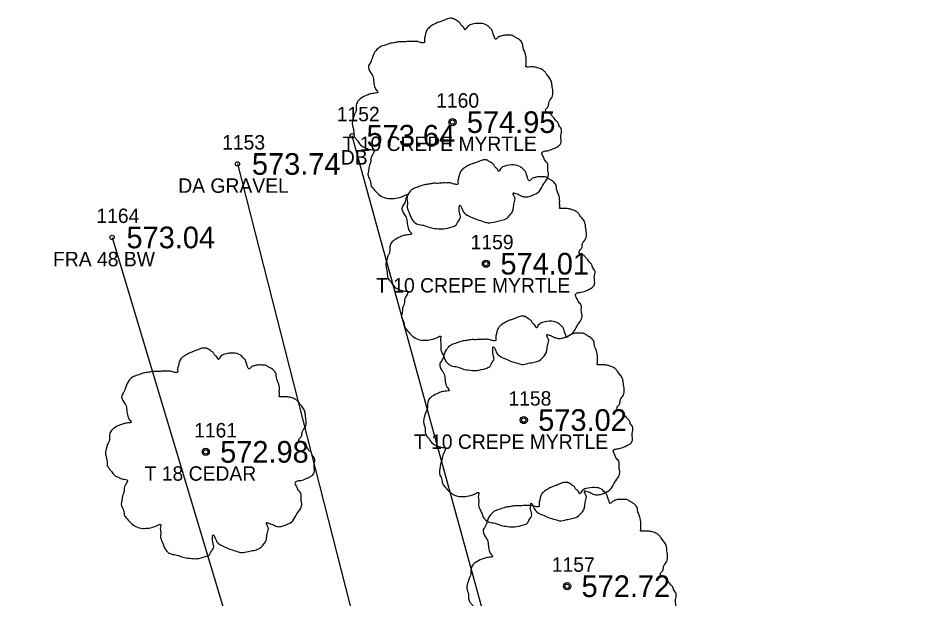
# Model space of a CAD drawing. Extents: x 1529475 to 1532053, y 876698 to 877911.
# Drawn here: x 1531018 to 1531081.1, y 877352.1 to 877392.4 of the extents above; entities that cross this region are included whole.
import ezdxf

# ---------------------------------------------------------------- set-up
doc = ezdxf.new("R2010")
doc.units = 0
for name, color, linetype in [('RD_EX_Driveway', 7, 'Continuous'), ('RD_EX_Driveway_txCode', 7, 'Continuous'), ('RD_EX_Fence_Other', 7, 'Continuous'), ('RD_EX_Fence_Other_txCode', 7, 'Continuous'), ('RD_EX_TX_Driveway_ELEV', 7, 'Continuous'), ('RD_EX_TX_Fence_Other_ELEV', 7, 'Continuous'), ('RD_EX_TX_VEG_ELEV', 7, 'Continuous'), ('RD_EX_VEG', 7, 'Continuous'), ('RD_EX_VEG_txCode', 7, 'Continuous'), ('RD_SMD_Locator', 7, 'Continuous')]:
    doc.layers.add(name, color=color, linetype=linetype)

msp = doc.modelspace()

# ---------------------------------------------------------------- linework, layer by layer
at = {"layer": 'RD_EX_Driveway'}
for points in [[(1531081.114, 877292.384), (1531071.715, 877299.875), (1531056.729, 877327.604), (1531041.174, 877384.235)], [(1531033.235, 877382.278), (1531052.392, 877307.085), (1531047.892, 877296.694), (1531044.444, 877291.901), (1531038.69, 877288.667)]]:
    msp.add_lwpolyline(points, dxfattribs=at)
at = {"layer": 'RD_EX_Fence_Other'}
msp.add_lwpolyline([(1531024.548, 877377.186), (1531037.254, 877334.843), (1531041.631, 877306.635), (1530974.749, 877305.169), (1530894.744, 877304.424), (1530859.113, 877317.256)], dxfattribs=at)
at = {"layer": 'RD_EX_VEG'}
for centre, radius in [((1531048.121, 877385.178), 0.25), ((1531048.108, 877385.16), 0.0001), ((1531050.446, 877375.367), 0.25), ((1531050.434, 877375.348), 0.0001), ((1531053.063, 877364.532), 0.25), ((1531053.051, 877364.513), 0.0001), ((1531031.035, 877362.328), 0.25), ((1531031.022, 877362.309), 0.0001), ((1531056.065, 877353.015), 0.25), ((1531056.052, 877352.996), 0.0001)]:
    msp.add_circle(centre, radius, dxfattribs=at)
for points in [[(1531048.253, 877392.346), (1531047.953, 877392.371), (1531047.628, 877392.271), (1531047.378, 877392.171), (1531047.153, 877392.096), (1531046.928, 877391.996), (1531046.629, 877391.821), (1531046.404, 877391.621), (1531046.279, 877391.371), (1531046.229, 877391.146), (1531046.179, 877390.871), (1531046.179, 877390.696), (1531046.054, 877390.671), (1531045.904, 877390.696), (1531045.654, 877390.771), (1531045.404, 877390.771), (1531045.154, 877390.771), (1531044.804, 877390.746), (1531044.454, 877390.746), (1531044.18, 877390.696), (1531043.855, 877390.646), (1531043.48, 877390.521), (1531043.13, 877390.396), (1531042.83, 877390.147), (1531042.58, 877389.672), (1531042.455, 877389.322), (1531042.305, 877389.072), (1531042.455, 877388.622), (1531042.63, 877388.272), (1531042.655, 877388.072), (1531042.73, 877387.648), (1531042.83, 877387.423), (1531042.955, 877387.223), (1531042.88, 877387.198), (1531042.505, 877387.148), (1531042.205, 877387.048), (1531041.781, 877386.823), (1531041.556, 877386.598), (1531041.456, 877386.273), (1531041.431, 877385.923), (1531041.331, 877385.724), (1531041.256, 877385.449), (1531041.231, 877385.374), (1531041.181, 877385.049), (1531041.281, 877384.599), (1531041.306, 877384.249), (1531041.431, 877384.024), (1531041.581, 877383.849), (1531041.756, 877383.599), (1531042.155, 877383.375), (1531042.48, 877383.275), (1531042.68, 877383.25), (1531042.505, 877382.75), (1531042.455, 877382.4), (1531042.33, 877382), (1531042.33, 877381.925), (1531042.28, 877381.45), (1531042.43, 877381.125), (1531042.505, 877380.751), (1531042.68, 877380.526), (1531042.955, 877380.226), (1531043.28, 877380.001), (1531043.78, 877379.876), (1531044.18, 877379.901), (1531044.754, 877380.076), (1531045.004, 877380.151), (1531044.979, 877379.976), (1531045.004, 877379.601), (1531045.004, 877379.176), (1531045.154, 877378.852), (1531045.254, 877378.577), (1531045.404, 877378.327), (1531045.729, 877378.102), (1531046.129, 877378.027), (1531046.554, 877377.877), (1531047.003, 877377.802), (1531047.503, 877377.777), (1531048.103, 877377.927), (1531048.378, 877378.052), (1531048.478, 877378.227), (1531048.678, 877378.602), (1531048.628, 877378.827), (1531048.653, 877379.426), (1531048.753, 877379.251), (1531048.928, 877378.901), (1531049.427, 877378.602), (1531049.827, 877378.427), (1531050.302, 877378.277), (1531050.602, 877378.202), (1531051.077, 877378.277), (1531051.451, 877378.352), (1531051.826, 877378.477), (1531052.126, 877378.752), (1531052.301, 877379.026), (1531052.351, 877379.301), (1531052.426, 877379.676), (1531052.476, 877379.851)], [(1531052.476, 877379.851), (1531052.401, 877380.026), (1531052.351, 877380.276), (1531052.426, 877380.251), (1531052.601, 877380.201), (1531052.876, 877380.076), (1531053.101, 877380.001), (1531053.426, 877380.026), (1531053.7, 877380.126), (1531054.15, 877380.401), (1531054.425, 877380.876), (1531054.7, 877381.275), (1531054.775, 877381.6), (1531054.725, 877381.825), (1531054.7, 877382.325), (1531054.5, 877382.575), (1531054.45, 877382.7), (1531054.35, 877383.1), (1531054.425, 877383.15), (1531054.7, 877383.2), (1531055.075, 877383.325), (1531055.35, 877383.449), (1531055.575, 877383.624), (1531055.65, 877383.849), (1531055.625, 877384.249), (1531055.675, 877384.649), (1531055.6, 877384.799), (1531055.5, 877384.949), (1531055.425, 877385.149), (1531055.275, 877385.299), (1531055.175, 877385.449), (1531055.075, 877385.549), (1531054.95, 877385.699), (1531054.775, 877385.823), (1531054.625, 877385.873), (1531054.575, 877386.023), (1531054.725, 877386.223), (1531054.775, 877386.323), (1531054.8, 877386.548), (1531055.025, 877386.898), (1531055.075, 877387.298), (1531055.025, 877387.723), (1531054.975, 877387.998), (1531054.825, 877388.272), (1531054.625, 877388.522), (1531054.5, 877388.697), (1531054.325, 877388.822), (1531054, 877388.947), (1531053.75, 877388.997), (1531053.401, 877388.997), (1531053.201, 877389.047), (1531053.226, 877389.097), (1531053.226, 877389.247), (1531053.226, 877389.522), (1531053.151, 877389.972), (1531053.001, 877390.471), (1531053.001, 877390.496), (1531052.901, 877390.746), (1531052.676, 877390.946), (1531052.501, 877391.046), (1531052.301, 877391.171), (1531052.051, 877391.196), (1531051.751, 877391.196), (1531051.476, 877391.146), (1531051.276, 877391.046), (1531051.102, 877390.921), (1531051.027, 877391.071), (1531050.927, 877391.371), (1531050.877, 877391.521), (1531050.727, 877391.696), (1531050.502, 877391.896), (1531050.052, 877392.021), (1531049.427, 877391.946), (1531049.127, 877391.746), (1531048.977, 877391.571), (1531048.928, 877391.696), (1531048.728, 877391.896), (1531048.628, 877392.071), (1531048.453, 877392.196), (1531048.303, 877392.296), (1531048.203, 877392.346)], [(1531050.578, 877382.534), (1531050.278, 877382.559), (1531049.953, 877382.459), (1531049.704, 877382.359), (1531049.479, 877382.284), (1531049.254, 877382.184), (1531048.954, 877382.009), (1531048.729, 877381.809), (1531048.604, 877381.559), (1531048.554, 877381.334), (1531048.504, 877381.06), (1531048.504, 877380.885), (1531048.379, 877380.86), (1531048.229, 877380.885), (1531047.979, 877380.96), (1531047.729, 877380.96), (1531047.479, 877380.96), (1531047.13, 877380.935), (1531046.78, 877380.935), (1531046.505, 877380.885), (1531046.18, 877380.835), (1531045.805, 877380.71), (1531045.455, 877380.585), (1531045.156, 877380.335), (1531044.906, 877379.86), (1531044.781, 877379.51), (1531044.631, 877379.26), (1531044.781, 877378.811), (1531044.956, 877378.461), (1531044.981, 877378.261), (1531045.056, 877377.836), (1531045.156, 877377.611), (1531045.28, 877377.411), (1531045.206, 877377.386), (1531044.831, 877377.336), (1531044.531, 877377.236), (1531044.106, 877377.011), (1531043.881, 877376.786), (1531043.781, 877376.462), (1531043.756, 877376.112), (1531043.656, 877375.912), (1531043.581, 877375.637), (1531043.556, 877375.562), (1531043.506, 877375.237), (1531043.606, 877374.787), (1531043.631, 877374.437), (1531043.756, 877374.213), (1531043.906, 877374.038), (1531044.081, 877373.788), (1531044.481, 877373.563), (1531044.806, 877373.463), (1531045.006, 877373.438), (1531044.831, 877372.938), (1531044.781, 877372.588), (1531044.656, 877372.188), (1531044.656, 877372.114), (1531044.606, 877371.639), (1531044.756, 877371.314), (1531044.831, 877370.939), (1531045.006, 877370.714), (1531045.28, 877370.414), (1531045.605, 877370.189), (1531046.105, 877370.064), (1531046.505, 877370.089), (1531047.08, 877370.264), (1531047.33, 877370.339), (1531047.305, 877370.164), (1531047.33, 877369.789), (1531047.33, 877369.365), (1531047.479, 877369.04), (1531047.579, 877368.765), (1531047.729, 877368.515), (1531048.054, 877368.29), (1531048.454, 877368.215), (1531048.879, 877368.065), (1531049.329, 877367.99), (1531049.828, 877367.965), (1531050.428, 877368.115), (1531050.703, 877368.24), (1531050.803, 877368.415), (1531051.003, 877368.79), (1531050.953, 877369.015), (1531050.978, 877369.615), (1531051.078, 877369.44), (1531051.253, 877369.09), (1531051.753, 877368.79), (1531052.152, 877368.615), (1531052.627, 877368.465), (1531052.927, 877368.39), (1531053.402, 877368.465), (1531053.777, 877368.54), (1531054.152, 877368.665), (1531054.451, 877368.94), (1531054.626, 877369.215), (1531054.676, 877369.49), (1531054.751, 877369.864), (1531054.801, 877370.039)], [(1531054.801, 877370.039), (1531054.726, 877370.214), (1531054.676, 877370.464), (1531054.751, 877370.439), (1531054.926, 877370.389), (1531055.201, 877370.264), (1531055.426, 877370.189), (1531055.751, 877370.214), (1531056.026, 877370.314), (1531056.476, 877370.589), (1531056.75, 877371.064), (1531057.025, 877371.464), (1531057.1, 877371.789), (1531057.05, 877372.014), (1531057.025, 877372.513), (1531056.825, 877372.763), (1531056.775, 877372.888), (1531056.675, 877373.288), (1531056.75, 877373.338), (1531057.025, 877373.388), (1531057.4, 877373.513), (1531057.675, 877373.638), (1531057.9, 877373.813), (1531057.975, 877374.038), (1531057.95, 877374.437), (1531058, 877374.837), (1531057.925, 877374.987), (1531057.825, 877375.137), (1531057.75, 877375.337), (1531057.6, 877375.487), (1531057.5, 877375.637), (1531057.4, 877375.737), (1531057.275, 877375.887), (1531057.1, 877376.012), (1531056.95, 877376.062), (1531056.9, 877376.212), (1531057.05, 877376.412), (1531057.1, 877376.512), (1531057.125, 877376.736), (1531057.35, 877377.086), (1531057.4, 877377.486), (1531057.35, 877377.911), (1531057.3, 877378.186), (1531057.15, 877378.461), (1531056.95, 877378.711), (1531056.825, 877378.886), (1531056.65, 877379.01), (1531056.326, 877379.135), (1531056.076, 877379.185), (1531055.726, 877379.185), (1531055.526, 877379.235), (1531055.551, 877379.285), (1531055.551, 877379.435), (1531055.551, 877379.71), (1531055.476, 877380.16), (1531055.326, 877380.66), (1531055.326, 877380.685), (1531055.226, 877380.935), (1531055.001, 877381.135), (1531054.826, 877381.234), (1531054.626, 877381.359), (1531054.376, 877381.384), (1531054.077, 877381.384), (1531053.802, 877381.334), (1531053.602, 877381.234), (1531053.427, 877381.11), (1531053.352, 877381.259), (1531053.252, 877381.559), (1531053.202, 877381.709), (1531053.052, 877381.884), (1531052.827, 877382.084), (1531052.377, 877382.209), (1531051.753, 877382.134), (1531051.453, 877381.934), (1531051.303, 877381.759), (1531051.253, 877381.884), (1531051.053, 877382.084), (1531050.953, 877382.259), (1531050.778, 877382.384), (1531050.628, 877382.484), (1531050.528, 877382.534)], [(1531053.195, 877371.699), (1531052.895, 877371.724), (1531052.57, 877371.624), (1531052.32, 877371.524), (1531052.096, 877371.449), (1531051.871, 877371.349), (1531051.571, 877371.174), (1531051.346, 877370.974), (1531051.221, 877370.724), (1531051.171, 877370.5), (1531051.121, 877370.225), (1531051.121, 877370.05), (1531050.996, 877370.025), (1531050.846, 877370.05), (1531050.596, 877370.125), (1531050.346, 877370.125), (1531050.096, 877370.125), (1531049.747, 877370.1), (1531049.397, 877370.1), (1531049.122, 877370.05), (1531048.797, 877370), (1531048.422, 877369.875), (1531048.072, 877369.75), (1531047.772, 877369.5), (1531047.523, 877369.025), (1531047.398, 877368.675), (1531047.248, 877368.425), (1531047.398, 877367.976), (1531047.573, 877367.626), (1531047.597, 877367.426), (1531047.672, 877367.001), (1531047.772, 877366.776), (1531047.897, 877366.576), (1531047.822, 877366.551), (1531047.448, 877366.501), (1531047.148, 877366.401), (1531046.723, 877366.176), (1531046.498, 877365.952), (1531046.398, 877365.627), (1531046.373, 877365.277), (1531046.273, 877365.077), (1531046.198, 877364.802), (1531046.173, 877364.727), (1531046.123, 877364.402), (1531046.223, 877363.952), (1531046.248, 877363.603), (1531046.373, 877363.378), (1531046.523, 877363.203), (1531046.698, 877362.953), (1531047.098, 877362.728), (1531047.423, 877362.628), (1531047.622, 877362.603), (1531047.448, 877362.103), (1531047.398, 877361.753), (1531047.273, 877361.354), (1531047.273, 877361.279), (1531047.223, 877360.804), (1531047.373, 877360.479), (1531047.448, 877360.104), (1531047.622, 877359.879), (1531047.897, 877359.579), (1531048.222, 877359.354), (1531048.722, 877359.229), (1531049.122, 877359.254), (1531049.697, 877359.429), (1531049.946, 877359.504), (1531049.921, 877359.329), (1531049.946, 877358.955), (1531049.946, 877358.53), (1531050.096, 877358.205), (1531050.196, 877357.93), (1531050.346, 877357.68), (1531050.671, 877357.455), (1531051.071, 877357.38), (1531051.496, 877357.23), (1531051.946, 877357.155), (1531052.445, 877357.13), (1531053.045, 877357.28), (1531053.32, 877357.405), (1531053.42, 877357.58), (1531053.62, 877357.955), (1531053.57, 877358.18), (1531053.595, 877358.78), (1531053.695, 877358.605), (1531053.87, 877358.255), (1531054.37, 877357.955), (1531054.769, 877357.78), (1531055.244, 877357.63), (1531055.544, 877357.555), (1531056.019, 877357.63), (1531056.394, 877357.705), (1531056.768, 877357.83), (1531057.068, 877358.105), (1531057.243, 877358.38), (1531057.293, 877358.655), (1531057.368, 877359.03), (1531057.418, 877359.204)], [(1531057.418, 877359.204), (1531057.343, 877359.379), (1531057.293, 877359.629), (1531057.368, 877359.604), (1531057.543, 877359.554), (1531057.818, 877359.429), (1531058.043, 877359.354), (1531058.368, 877359.379), (1531058.643, 877359.479), (1531059.092, 877359.754), (1531059.367, 877360.229), (1531059.642, 877360.629), (1531059.717, 877360.954), (1531059.667, 877361.179), (1531059.642, 877361.678), (1531059.442, 877361.928), (1531059.392, 877362.053), (1531059.292, 877362.453), (1531059.367, 877362.503), (1531059.642, 877362.553), (1531060.017, 877362.678), (1531060.292, 877362.803), (1531060.517, 877362.978), (1531060.592, 877363.203), (1531060.567, 877363.603), (1531060.617, 877364.002), (1531060.542, 877364.152), (1531060.442, 877364.302), (1531060.367, 877364.502), (1531060.217, 877364.652), (1531060.117, 877364.802), (1531060.017, 877364.902), (1531059.892, 877365.052), (1531059.717, 877365.177), (1531059.567, 877365.227), (1531059.517, 877365.377), (1531059.667, 877365.577), (1531059.717, 877365.677), (1531059.742, 877365.902), (1531059.967, 877366.251), (1531060.017, 877366.651), (1531059.967, 877367.076), (1531059.917, 877367.351), (1531059.767, 877367.626), (1531059.567, 877367.876), (1531059.442, 877368.051), (1531059.267, 877368.176), (1531058.943, 877368.301), (1531058.693, 877368.35), (1531058.343, 877368.35), (1531058.143, 877368.4), (1531058.168, 877368.45), (1531058.168, 877368.6), (1531058.168, 877368.875), (1531058.093, 877369.325), (1531057.943, 877369.825), (1531057.943, 877369.85), (1531057.843, 877370.1), (1531057.618, 877370.3), (1531057.443, 877370.4), (1531057.243, 877370.525), (1531056.993, 877370.55), (1531056.694, 877370.55), (1531056.419, 877370.5), (1531056.219, 877370.4), (1531056.044, 877370.275), (1531055.969, 877370.425), (1531055.869, 877370.724), (1531055.819, 877370.874), (1531055.669, 877371.049), (1531055.444, 877371.249), (1531054.994, 877371.374), (1531054.37, 877371.299), (1531054.07, 877371.099), (1531053.92, 877370.924), (1531053.87, 877371.049), (1531053.67, 877371.249), (1531053.57, 877371.424), (1531053.395, 877371.549), (1531053.245, 877371.649), (1531053.145, 877371.699)], [(1531031.167, 877369.495), (1531030.867, 877369.52), (1531030.542, 877369.42), (1531030.292, 877369.32), (1531030.067, 877369.245), (1531029.842, 877369.145), (1531029.542, 877368.97), (1531029.317, 877368.77), (1531029.192, 877368.52), (1531029.142, 877368.295), (1531029.092, 877368.02), (1531029.092, 877367.845), (1531028.968, 877367.82), (1531028.818, 877367.845), (1531028.568, 877367.92), (1531028.318, 877367.92), (1531028.068, 877367.92), (1531027.718, 877367.895), (1531027.368, 877367.895), (1531027.093, 877367.845), (1531026.768, 877367.796), (1531026.394, 877367.671), (1531026.044, 877367.546), (1531025.744, 877367.296), (1531025.494, 877366.821), (1531025.369, 877366.471), (1531025.219, 877366.221), (1531025.369, 877365.771), (1531025.544, 877365.422), (1531025.569, 877365.222), (1531025.644, 877364.797), (1531025.744, 877364.572), (1531025.869, 877364.372), (1531025.794, 877364.347), (1531025.419, 877364.297), (1531025.119, 877364.197), (1531024.694, 877363.972), (1531024.469, 877363.747), (1531024.369, 877363.422), (1531024.345, 877363.073), (1531024.245, 877362.873), (1531024.17, 877362.598), (1531024.145, 877362.523), (1531024.095, 877362.198), (1531024.195, 877361.748), (1531024.22, 877361.398), (1531024.345, 877361.173), (1531024.494, 877360.999), (1531024.669, 877360.749), (1531025.069, 877360.524), (1531025.394, 877360.424), (1531025.594, 877360.399), (1531025.419, 877359.899), (1531025.369, 877359.549), (1531025.244, 877359.149), (1531025.244, 877359.074), (1531025.194, 877358.6), (1531025.344, 877358.275), (1531025.419, 877357.9), (1531025.594, 877357.675), (1531025.869, 877357.375), (1531026.194, 877357.15), (1531026.694, 877357.025), (1531027.093, 877357.05), (1531027.668, 877357.225), (1531027.918, 877357.3), (1531027.893, 877357.125), (1531027.918, 877356.75), (1531027.918, 877356.326), (1531028.068, 877356.001), (1531028.168, 877355.726), (1531028.318, 877355.476), (1531028.643, 877355.251), (1531029.042, 877355.176), (1531029.467, 877355.026), (1531029.917, 877354.951), (1531030.417, 877354.926), (1531031.017, 877355.076), (1531031.291, 877355.201), (1531031.391, 877355.376), (1531031.591, 877355.751), (1531031.541, 877355.976), (1531031.566, 877356.575), (1531031.666, 877356.4), (1531031.841, 877356.051), (1531032.341, 877355.751), (1531032.741, 877355.576), (1531033.216, 877355.426), (1531033.516, 877355.351), (1531033.99, 877355.426), (1531034.365, 877355.501), (1531034.74, 877355.626), (1531035.04, 877355.901), (1531035.215, 877356.176), (1531035.265, 877356.45), (1531035.34, 877356.825), (1531035.39, 877357)], [(1531035.39, 877357), (1531035.315, 877357.175), (1531035.265, 877357.425), (1531035.34, 877357.4), (1531035.515, 877357.35), (1531035.79, 877357.225), (1531036.014, 877357.15), (1531036.339, 877357.175), (1531036.614, 877357.275), (1531037.064, 877357.55), (1531037.339, 877358.025), (1531037.614, 877358.425), (1531037.689, 877358.749), (1531037.639, 877358.974), (1531037.614, 877359.474), (1531037.414, 877359.724), (1531037.364, 877359.849), (1531037.264, 877360.249), (1531037.339, 877360.299), (1531037.614, 877360.349), (1531037.989, 877360.474), (1531038.263, 877360.599), (1531038.488, 877360.774), (1531038.563, 877360.999), (1531038.538, 877361.398), (1531038.588, 877361.798), (1531038.513, 877361.948), (1531038.413, 877362.098), (1531038.338, 877362.298), (1531038.188, 877362.448), (1531038.089, 877362.598), (1531037.989, 877362.698), (1531037.864, 877362.848), (1531037.689, 877362.973), (1531037.539, 877363.023), (1531037.489, 877363.173), (1531037.639, 877363.372), (1531037.689, 877363.472), (1531037.714, 877363.697), (1531037.939, 877364.047), (1531037.989, 877364.447), (1531037.939, 877364.872), (1531037.889, 877365.147), (1531037.739, 877365.422), (1531037.539, 877365.671), (1531037.414, 877365.846), (1531037.239, 877365.971), (1531036.914, 877366.096), (1531036.664, 877366.146), (1531036.314, 877366.146), (1531036.114, 877366.196), (1531036.139, 877366.246), (1531036.139, 877366.396), (1531036.139, 877366.671), (1531036.064, 877367.121), (1531035.914, 877367.621), (1531035.914, 877367.646), (1531035.814, 877367.895), (1531035.59, 877368.095), (1531035.415, 877368.195), (1531035.215, 877368.32), (1531034.965, 877368.345), (1531034.665, 877368.345), (1531034.39, 877368.295), (1531034.19, 877368.195), (1531034.015, 877368.07), (1531033.94, 877368.22), (1531033.84, 877368.52), (1531033.79, 877368.67), (1531033.64, 877368.845), (1531033.416, 877369.045), (1531032.966, 877369.17), (1531032.341, 877369.095), (1531032.041, 877368.895), (1531031.891, 877368.72), (1531031.841, 877368.845), (1531031.641, 877369.045), (1531031.541, 877369.22), (1531031.366, 877369.345), (1531031.217, 877369.445), (1531031.117, 877369.495)], [(1531056.197, 877360.182), (1531055.897, 877360.207), (1531055.572, 877360.107), (1531055.322, 877360.007), (1531055.097, 877359.932), (1531054.872, 877359.832), (1531054.572, 877359.658), (1531054.347, 877359.458), (1531054.222, 877359.208), (1531054.172, 877358.983), (1531054.123, 877358.708), (1531054.123, 877358.533), (1531053.998, 877358.508), (1531053.848, 877358.533), (1531053.598, 877358.608), (1531053.348, 877358.608), (1531053.098, 877358.608), (1531052.748, 877358.583), (1531052.398, 877358.583), (1531052.123, 877358.533), (1531051.799, 877358.483), (1531051.424, 877358.358), (1531051.074, 877358.233), (1531050.774, 877357.983), (1531050.524, 877357.509), (1531050.399, 877357.159), (1531050.249, 877356.909), (1531050.399, 877356.459), (1531050.574, 877356.109), (1531050.599, 877355.909), (1531050.674, 877355.484), (1531050.774, 877355.26), (1531050.899, 877355.06), (1531050.824, 877355.035), (1531050.449, 877354.985), (1531050.149, 877354.885), (1531049.724, 877354.66), (1531049.5, 877354.435), (1531049.4, 877354.11), (1531049.375, 877353.76), (1531049.275, 877353.56), (1531049.2, 877353.285), (1531049.175, 877353.21), (1531049.125, 877352.886), (1531049.225, 877352.436), (1531049.25, 877352.086), (1531049.375, 877351.861), (1531049.525, 877351.686), (1531049.699, 877351.436), (1531050.099, 877351.211), (1531050.424, 877351.111), (1531050.624, 877351.086), (1531050.449, 877350.587), (1531050.399, 877350.237), (1531050.274, 877349.837), (1531050.274, 877349.762), (1531050.224, 877349.287), (1531050.374, 877348.962), (1531050.449, 877348.587), (1531050.624, 877348.363), (1531050.899, 877348.063), (1531051.224, 877347.838), (1531051.724, 877347.713), (1531052.123, 877347.738), (1531052.698, 877347.913), (1531052.948, 877347.988), (1531052.923, 877347.813), (1531052.948, 877347.438), (1531052.948, 877347.013), (1531053.098, 877346.688), (1531053.198, 877346.413), (1531053.348, 877346.163), (1531053.673, 877345.939), (1531054.073, 877345.864), (1531054.497, 877345.714), (1531054.947, 877345.639), (1531055.447, 877345.614), (1531056.047, 877345.764), (1531056.322, 877345.889), (1531056.422, 877346.064), (1531056.621, 877346.438), (1531056.571, 877346.663), (1531056.596, 877347.263), (1531056.696, 877347.088), (1531056.871, 877346.738), (1531057.371, 877346.438), (1531057.771, 877346.263), (1531058.246, 877346.113), (1531058.546, 877346.039), (1531059.02, 877346.113), (1531059.395, 877346.188), (1531059.77, 877346.313), (1531060.07, 877346.588), (1531060.245, 877346.863), (1531060.295, 877347.138), (1531060.37, 877347.513), (1531060.42, 877347.688)], [(1531060.42, 877347.688), (1531060.345, 877347.863), (1531060.295, 877348.113), (1531060.37, 877348.088), (1531060.545, 877348.038), (1531060.82, 877347.913), (1531061.045, 877347.838), (1531061.369, 877347.863), (1531061.644, 877347.963), (1531062.094, 877348.238), (1531062.369, 877348.712), (1531062.644, 877349.112), (1531062.719, 877349.437), (1531062.669, 877349.662), (1531062.644, 877350.162), (1531062.444, 877350.412), (1531062.394, 877350.537), (1531062.294, 877350.936), (1531062.369, 877350.986), (1531062.644, 877351.036), (1531063.019, 877351.161), (1531063.294, 877351.286), (1531063.518, 877351.461), (1531063.593, 877351.686), (1531063.568, 877352.086), (1531063.618, 877352.486), (1531063.543, 877352.636), (1531063.443, 877352.786), (1531063.368, 877352.986), (1531063.219, 877353.135), (1531063.119, 877353.285), (1531063.019, 877353.385), (1531062.894, 877353.535), (1531062.719, 877353.66), (1531062.569, 877353.71), (1531062.519, 877353.86), (1531062.669, 877354.06), (1531062.719, 877354.16), (1531062.744, 877354.385), (1531062.969, 877354.735), (1531063.019, 877355.135), (1531062.969, 877355.559), (1531062.919, 877355.834), (1531062.769, 877356.109), (1531062.569, 877356.359), (1531062.444, 877356.534), (1531062.269, 877356.659), (1531061.944, 877356.784), (1531061.694, 877356.834), (1531061.344, 877356.834), (1531061.144, 877356.884), (1531061.169, 877356.934), (1531061.169, 877357.084), (1531061.169, 877357.359), (1531061.094, 877357.808), (1531060.945, 877358.308), (1531060.945, 877358.333), (1531060.845, 877358.583), (1531060.62, 877358.783), (1531060.445, 877358.883), (1531060.245, 877359.008), (1531059.995, 877359.033), (1531059.695, 877359.033), (1531059.42, 877358.983), (1531059.22, 877358.883), (1531059.045, 877358.758), (1531058.97, 877358.908), (1531058.87, 877359.208), (1531058.82, 877359.358), (1531058.671, 877359.533), (1531058.446, 877359.733), (1531057.996, 877359.857), (1531057.371, 877359.783), (1531057.071, 877359.583), (1531056.921, 877359.408), (1531056.871, 877359.533), (1531056.671, 877359.733), (1531056.571, 877359.907), (1531056.397, 877360.032), (1531056.247, 877360.132), (1531056.147, 877360.182)]]:
    msp.add_spline(points, degree=3, dxfattribs=at)
at = {"layer": 'RD_SMD_Locator'}
for centre in [(1531048.121, 877385.178), (1531041.174, 877384.235), (1531033.235, 877382.278), (1531024.548, 877377.186), (1531050.446, 877375.367), (1531053.063, 877364.532), (1531031.035, 877362.328), (1531056.065, 877353.015)]:
    msp.add_circle(centre, 0.15, dxfattribs=at)

# ---------------------------------------------------------------- texts
at = {"layer": 'RD_EX_Driveway_txCode'}
for s, p in [('1152', (1531040.111, 877385.235)), ('1153', (1531032.172, 877383.278)), ('DB', (1531040.394, 877382.235)), ('DA GRAVEL', (1531029.133, 877380.278))]:
    msp.add_text(s, height=1, dxfattribs=at).set_placement(p)
at = {"layer": 'RD_EX_Fence_Other_txCode'}
for s, p in [('1164', (1531023.461, 877378.186)), ('FRA 48 BW', (1531020.461, 877375.186))]:
    msp.add_text(s, height=1, dxfattribs=at).set_placement(p)
at = {"layer": 'RD_EX_TX_Driveway_ELEV'}
for s, p in [('573.64', (1531042.174, 877383.485)), ('573.74', (1531034.235, 877381.528))]:
    msp.add_text(s, height=1.5, dxfattribs=at).set_placement(p)
at = {"layer": 'RD_EX_TX_Fence_Other_ELEV'}
msp.add_text('573.04', height=1.5, dxfattribs=at).set_placement((1531025.548, 877376.436))
at = {"layer": 'RD_EX_TX_VEG_ELEV'}
for s, p in [('574.95', (1531049.121, 877384.428)), ('574.01', (1531051.446, 877374.617)), ('573.02', (1531054.063, 877363.782)), ('572.98', (1531032.035, 877361.578)), ('572.72', (1531057.065, 877352.265))]:
    msp.add_text(s, height=1.5, dxfattribs=at).set_placement(p)
at = {"layer": 'RD_EX_VEG_txCode'}
for s, p in [('1160', (1531046.995, 877386.178)), ('T 10 CREPE MYRTLE', (1531040.511, 877383.178)), ('1159', (1531049.383, 877376.367)), ('T 10 CREPE MYRTLE', (1531042.836, 877373.367)), ('1158', (1531052, 877365.532)), ('1161', (1531030.231, 877363.328)), ('T 10 CREPE MYRTLE', (1531045.453, 877362.532)), ('T 18 CEDAR', (1531026.806, 877360.328)), ('1157', (1531055.002, 877354.015))]:
    msp.add_text(s, height=1, dxfattribs=at).set_placement(p)

doc.saveas('drawing.dxf')
